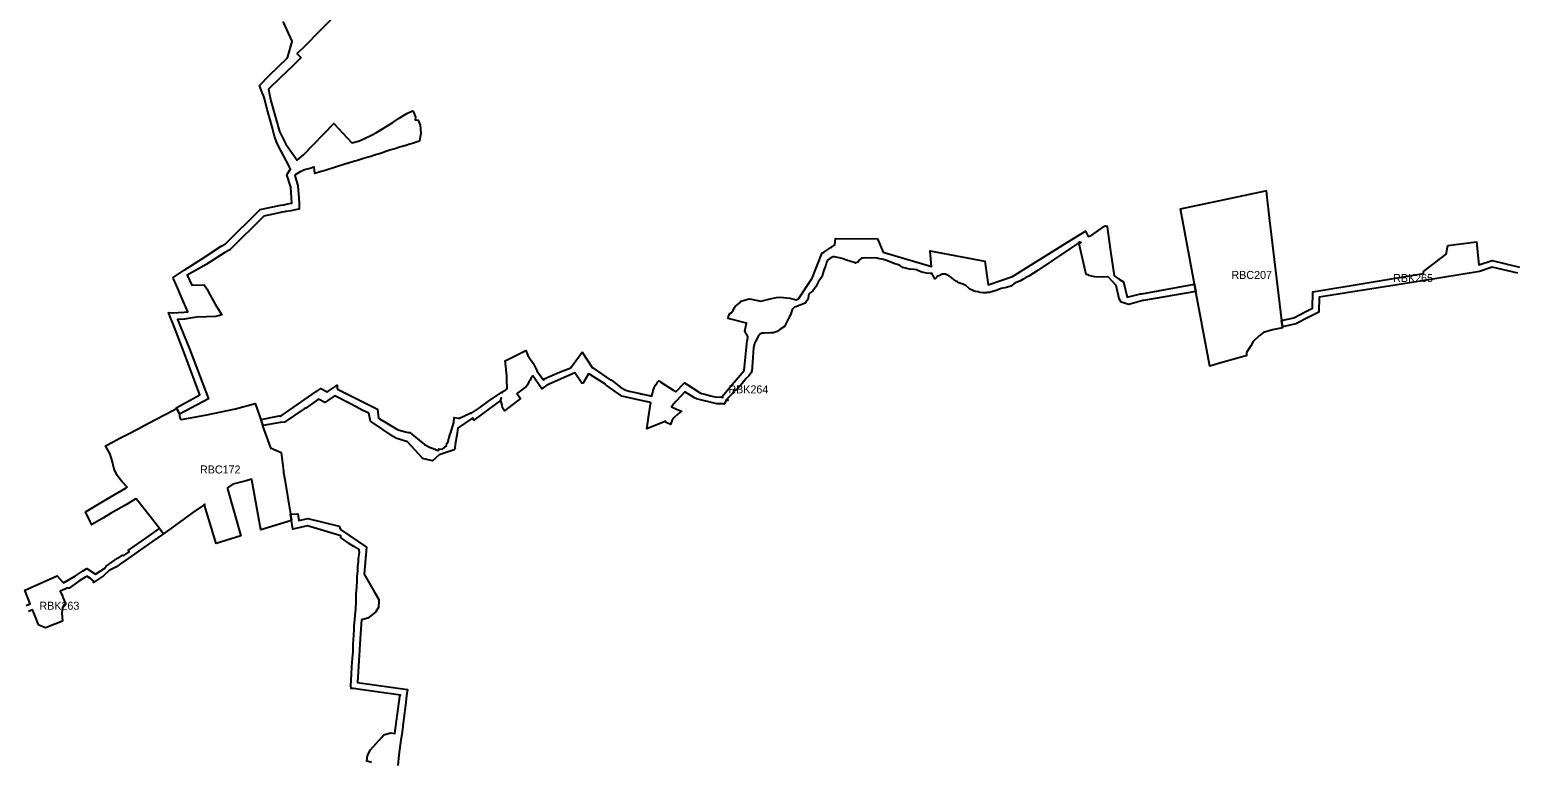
# Model space of a CAD drawing. Extents: x -559776 to -467147, y -1204122 to -1132159.
# Drawn here: x -531983 to -522720, y -1164141 to -1159572 of the extents above; entities that cross this region are included whole.
import ezdxf

# ---------------------------------------------------------------- set-up
doc = ezdxf.new("R2010")
doc.units = 0
doc.layers.add('regionalni_biocentrum_biokoridor', color=7, linetype='Continuous')

msp = doc.modelspace()

# ---------------------------------------------------------------- linework, layer by layer
at = {"layer": 'regionalni_biocentrum_biokoridor'}
for points in [[(-530073.87, -1159482.72), (-530173.93, -1159583.23), (-530265.2, -1159675.35), (-530307.03, -1159716.85), (-530312.02, -1159723.48), (-530289.76, -1159745.15), (-530291.86, -1159749.98), (-530342.2, -1159799.08), (-530415.63, -1159870.42), (-530491.07, -1159944.46), (-530485.06, -1159976.78), (-530475.57, -1160017.31), (-530421.45, -1160208.89), (-530382.52, -1160287.19), (-530311.69, -1160387.08), (-530272.65, -1160352.76), (-530082.99, -1160157.02), (-529971.24, -1160279.21), (-529923.41, -1160265.87), (-529852.16, -1160233.62), (-529817.21, -1160213.2), (-529714.58, -1160151.17), (-529674.14, -1160124.8), (-529626.69, -1160095.91), (-529590.94, -1160078.02), (-529589.97, -1160080.45), (-529587.15, -1160083), (-529584.33, -1160086.06), (-529579.15, -1160100.89), (-529573.27, -1160117.84), (-529574.41, -1160134.9), (-529556.31, -1160137.73), (-529543.15, -1160167.55), (-529540.33, -1160215.23), (-529547.86, -1160268.9), (-529569.54, -1160275.49), (-529584.25, -1160279.86), (-529599.78, -1160285.04), (-529616.1, -1160289.37), (-529631.63, -1160294.52), (-529639.54, -1160296.97), (-529644.42, -1160298.29), (-529649.27, -1160299.59), (-529656.9, -1160302.32), (-529663.98, -1160303.96), (-529678.96, -1160308.32), (-529693.95, -1160313.23), (-529726, -1160323.46), (-529758.04, -1160333.68), (-529765, -1160335.87), (-529779.39, -1160340.25), (-529786.12, -1160342.41), (-529792.47, -1160344.61), (-529807.74, -1160349.4), (-529822.14, -1160354), (-529826.72, -1160355.31), (-529835.24, -1160357.84), (-529839.36, -1160359.16), (-529852.67, -1160363.73), (-529868.61, -1160368.13), (-529883.44, -1160372.48), (-529897.83, -1160377.02), (-529909.84, -1160380.76), (-529923.12, -1160385.09), (-529936, -1160388.41), (-529950.83, -1160392.8), (-529965.23, -1160397.98), (-529980.03, -1160402.17), (-529994.87, -1160407.02), (-530000.76, -1160408.53), (-530008.17, -1160410.68), (-530136.74, -1160451.09), (-530153.01, -1160456.15), (-530161.64, -1160458.76), (-530201.96, -1160470.79), (-530206.75, -1160430.37), (-530207.71, -1160431.01), (-530231.46, -1160439.72), (-530259.91, -1160445.37), (-530293.25, -1160460.2), (-530323.87, -1160478.35), (-530327.08, -1160483.74), (-530307.97, -1160548.09), (-530300.59, -1160654.36), (-530299.85, -1160692.77), (-530304.95, -1160693.97), (-530322.79, -1160697.27), (-530350.66, -1160702.5), (-530382.37, -1160708.54), (-530389.51, -1160709.64), (-530406.95, -1160712.26), (-530414.77, -1160713.77), (-530521.17, -1160736.48), (-530732.84, -1160946.58), (-530763.94, -1160962.99), (-530879.59, -1161038.16), (-530998.66, -1161105.71), (-530969.81, -1161168.24), (-530893.01, -1161165.11), (-530876.02, -1161189.88), (-530856.17, -1161230.71), (-530823.87, -1161285.51), (-530783.56, -1161352.29), (-530820.71, -1161363.03), (-530938.54, -1161366.64), (-530980.63, -1161372.65), (-531015.83, -1161380.36), (-531059.99, -1161382.27), (-530985.44, -1161565.03), (-530866.4, -1161876.46), (-531046.89, -1161973.38), (-531062.73, -1161942.81), (-531065.32, -1161938.2), (-531063.15, -1161931.23), (-530919.3, -1161852.41), (-531020.31, -1161583.07), (-531088.54, -1161405.05), (-531100.87, -1161376.25), (-531116.5, -1161337.78), (-531094.72, -1161340.12), (-531018.58, -1161335.45), (-530995.61, -1161334.04), (-531033.9, -1161242.35), (-531056.76, -1161187.63), (-531066.01, -1161169.84), (-531084.15, -1161127.21), (-531085.88, -1161119.5), (-531080.45, -1161116.09), (-531017.02, -1161074.67), (-530904.22, -1161000.49), (-530786.75, -1160924.15), (-530759.77, -1160909.92), (-530543.49, -1160695.23), (-530423.74, -1160669.67), (-530414.55, -1160667.89), (-530396.27, -1160665.15), (-530390.01, -1160664.19), (-530359.02, -1160658.28), (-530345.6, -1160655.76), (-530352.52, -1160556.15), (-530375.82, -1160477.66), (-530354.51, -1160441.83), (-530355.93, -1160439.82), (-530360.28, -1160429.78), (-530359.42, -1160429.03), (-530378.05, -1160392.19), (-530412.88, -1160330.89), (-530438.68, -1160279.27), (-530454.4, -1160237.16), (-530470.99, -1160172.43), (-530477.45, -1160150.08), (-530500.11, -1160070.77), (-530515.64, -1160001.9), (-530524.65, -1159977.42), (-530525.1, -1159977.87), (-530526.58, -1159975.01), (-530528.68, -1159969.96), (-530530.36, -1159964.29), (-530534.56, -1159953.99), (-530538.55, -1159942.85), (-530540.23, -1159938.23), (-530542.96, -1159930.87), (-530547.51, -1159919.84), (-530488.99, -1159860.66), (-530371.48, -1159747.9), (-530343.23, -1159645.57), (-530343.61, -1159644.79), (-530399.82, -1159520.7)], [(-522686, -1161093), (-522847, -1161055), (-522926, -1161083), (-523269, -1161138), (-523927.07, -1161241.62), (-523929, -1161336), (-523992, -1161368), (-524072, -1161409), (-524156.7, -1161428.16), (-524161.51, -1161388.23), (-524085.75, -1161371.1), (-524010.18, -1161332.37), (-523968.5, -1161311.2), (-523966.41, -1161208.65), (-523276, -1161095), (-523276, -1161087), (-523275.31, -1161082.86), (-523134, -1160974), (-523124, -1160919), (-522945, -1160897), (-522930.24, -1161041.47), (-522845.6, -1161014.23), (-522674.52, -1161054.61)], [(-529848.43, -1164149.26), (-529876.9, -1164140), (-529872.1, -1164105.5), (-529854.3, -1164068.9), (-529784.05, -1163990.31), (-529770.9, -1163975.6), (-529728.1, -1163964), (-529700.91, -1163967.51), (-529669.9, -1163736.2), (-529666.94, -1163727.4), (-529919.25, -1163692.42), (-529960.5, -1163686.7), (-529973.7, -1163685.4), (-529973.8, -1163684.91), (-529976.9, -1163669.2), (-529973.3, -1163599.2), (-529970.3, -1163548.9), (-529966.7, -1163499.5), (-529963, -1163454.4), (-529961.6, -1163408.7), (-529959.8, -1163384), (-529956.6, -1163318.7), (-529954.96, -1163294.49), (-529952.5, -1163258.2), (-529952, -1163253.4), (-529947.1, -1163207.4), (-529946.1, -1163193.1), (-529943.3, -1163141.1), (-529943.4, -1163125.6), (-529943.83, -1163101.75), (-529943.9, -1163097.9), (-529939.5, -1163051.7), (-529937.7, -1163017), (-529937.7, -1163016.5), (-529937.8, -1163008.1), (-529938.1, -1162989), (-529935.5, -1162967.7), (-529934.1, -1162956.3), (-529933.3, -1162945.4), (-529932.5, -1162934.5), (-529932.1, -1162918.3), (-529931.9, -1162915.9), (-529929.5, -1162890), (-529928.4, -1162878.6), (-529926.2, -1162863), (-529922.7, -1162837.4), (-529923.7, -1162823.5), (-529929.5, -1162817), (-529958.7, -1162799.5), (-529959.01, -1162799.3), (-529988.4, -1162780.9), (-529994.3, -1162776.7), (-530029.2, -1162751.6), (-530038.5, -1162744.4), (-530039.3, -1162733.43), (-530247.03, -1162671.46), (-530338.39, -1162691.45), (-530353.73, -1162598.53), (-530308.62, -1162596.24), (-530301.77, -1162637.37), (-530245.48, -1162625.06), (-530049.42, -1162672.5), (-530042.2, -1162693.5), (-529879.4, -1162803.6), (-529893.4, -1162972.8), (-529828.39, -1163084.68), (-529801.3, -1163131.3), (-529801.95, -1163140.59), (-529804.7, -1163180.2), (-529822.8, -1163209.8), (-529870, -1163247.3), (-529910.3, -1163258.5), (-529915.69, -1163342.26), (-529935.5, -1163649.8), (-529921.4, -1163651.76), (-529622.9, -1163693.2), (-529628, -1163732.8), (-529635.36, -1163789.97), (-529645.5, -1163868.8), (-529659.2, -1163972.9), (-529663.8, -1164008), (-529676.8, -1164100.5), (-529684, -1164167.39)], [(-532006.16, -1163169.09), (-531979.28, -1163157.62), (-532013.29, -1163071.8), (-531812.11, -1162982), (-531779.85, -1163018.81), (-531772.86, -1163026.96), (-531697.86, -1162982.32), (-531653.03, -1162954.34), (-531626.71, -1162936.97), (-531571.21, -1162972.5), (-531514.22, -1162935.37), (-531505.73, -1162921.97), (-531435.5, -1162872.33), (-531435, -1162871.98), (-531430.46, -1162871.48), (-531403.7, -1162853.35), (-531394.29, -1162855.75), (-531361.31, -1162833), (-531367.16, -1162824.64), (-531235.86, -1162733.02), (-531172.62, -1162688.05), (-531148.02, -1162719.64), (-531212.86, -1162765.75), (-531368.06, -1162874.05), (-531416.85, -1162908.09), (-531439.96, -1162927.6), (-531485.72, -1162950.05), (-531521.12, -1162982), (-531584.16, -1163024.31), (-531584.98, -1163013.33), (-531603.56, -1163000.06), (-531626.94, -1162985.05), (-531631.41, -1162988.01), (-531675.53, -1163015.54), (-531736.99, -1163058.85), (-531750.04, -1163060.29), (-531792.64, -1163078.32), (-531777.09, -1163113.97), (-531773.39, -1163122.41), (-531759.14, -1163154.96), (-531769.67, -1163164.23), (-531777.26, -1163182.13), (-531782.78, -1163212.82), (-531778.01, -1163265.99), (-531825.7, -1163284.72), (-531884.03, -1163307.75), (-531925.32, -1163290.15), (-531930.27, -1163282.66), (-531945.52, -1163244.92), (-531961.28, -1163204.12), (-531964.83, -1163194.94), (-531990.38, -1163205.84)]]:
    msp.add_lwpolyline(points, dxfattribs=at)
for points in [[(-524555.42, -1161657.29), (-524611, -1161673), (-524698, -1161209), (-524698.29, -1161207.44), (-524706, -1161166), (-524706.72, -1161162.07), (-524793.46, -1160689.89), (-524527.69, -1160634.25), (-524261.92, -1160578.61), (-524259, -1160578), (-524254.15, -1160618.33), (-524238.57, -1160747.8), (-524161.51, -1161388.23), (-524156.7, -1161428.16), (-524156, -1161434), (-524218, -1161446), (-524274, -1161464), (-524301, -1161484), (-524339, -1161520), (-524354, -1161546), (-524381, -1161588), (-524381, -1161608), (-524386, -1161609.41), (-524428.97, -1161621.56)], [(-525251.67, -1160802.38), (-525230.16, -1160954.79), (-525208.24, -1161110.05), (-525173.8, -1161131.34), (-525148.72, -1161146.83), (-525125.77, -1161242.23), (-525043.17, -1161222.36), (-525041.31, -1161222.03), (-525035.2, -1161220.93), (-524706.72, -1161162.07), (-524706, -1161166), (-524698.29, -1161207.44), (-525024.34, -1161263.15), (-525028.95, -1161264.36), (-525116.48, -1161287.3), (-525163.92, -1161273.77), (-525176.94, -1161253.47), (-525194.92, -1161168.86), (-525218.83, -1161143.8), (-525246.2, -1161115.09), (-525249.44, -1161115.32), (-525276.22, -1161117.26), (-525327.81, -1161115.03), (-525366.48, -1161106.46), (-525367.14, -1161103.45), (-525382.06, -1161100.29), (-525427.07, -1160909.49), (-525413.89, -1160900.56), (-525422.34, -1160898.14), (-525430.85, -1160903.92), (-525452.97, -1160918.95), (-525485.24, -1160940.69), (-525682.3, -1161073.47), (-525740.07, -1161111.36), (-525759.19, -1161119.86), (-525773.15, -1161128.32), (-525796.97, -1161141.74), (-525825.77, -1161153.5), (-525853.99, -1161172.8), (-525881.5, -1161182.68), (-525913.07, -1161187.38), (-525938.48, -1161198.11), (-525944.03, -1161199.99), (-525987.61, -1161213.03), (-525999.68, -1161214.09), (-526004.76, -1161215.01), (-526008.1, -1161214.82), (-526012.95, -1161215.25), (-526027.22, -1161214.62), (-526046.87, -1161213.75), (-526057.67, -1161210.1), (-526075.78, -1161206.53), (-526081.87, -1161204.44), (-526094.34, -1161199.12), (-526108.62, -1161191.97), (-526115.77, -1161186.04), (-526134.92, -1161169.15), (-526152.85, -1161160.33), (-526177.47, -1161152.42), (-526187.13, -1161146.72), (-526195.87, -1161141.84), (-526206.48, -1161134.38), (-526222.98, -1161122.18), (-526235.6, -1161111.56), (-526260.55, -1161098.65), (-526281.49, -1161097.93), (-526300.93, -1161110.05), (-526311.29, -1161111.69), (-526317.1, -1161119.15), (-526328, -1161127.43), (-526338.43, -1161107.88), (-526348.99, -1161096.62), (-526344.1, -1161096.66), (-526348.13, -1161096.06), (-526345.36, -1161094.27), (-526348.77, -1161094.33), (-526357.86, -1161093.98), (-526379.65, -1161093.16), (-526415.84, -1161084.57), (-526441.98, -1161071.16), (-526456.54, -1161070.35), (-526485.53, -1161067.15), (-526528.89, -1161056.61), (-526547.67, -1161044.12), (-526560.79, -1161038.73), (-526578.8, -1161035.2), (-526603.29, -1161024.59), (-526629.63, -1161014.46), (-526643.03, -1161009.3), (-526644.73, -1161008.66), (-526644.99, -1161008.56), (-526649.05, -1161007.2), (-526683.06, -1161000.25), (-526688.72, -1160999.31), (-526706.36, -1160996.47), (-526733.26, -1160999.28), (-526759.03, -1160996.74), (-526776.07, -1160998.12), (-526785.95, -1160998.94), (-526801.41, -1161010.94), (-526803.17, -1161012.31), (-526806.71, -1161019.01), (-526808.91, -1161023.17), (-526816.14, -1161026.29), (-526823.25, -1161029.35), (-526826.41, -1161028.31), (-526886.88, -1161008.52), (-526907.89, -1161001.64), (-526955.59, -1160991.22), (-526963.71, -1160991.15), (-526974.41, -1160994.57), (-526984.21, -1161000.65), (-526998.08, -1161010.73), (-527005.85, -1161025.15), (-527009.51, -1161042.78), (-527020.74, -1161074.46), (-527027.01, -1161094.71), (-527032.54, -1161112.56), (-527037.73, -1161121.73), (-527056.06, -1161148.51), (-527070.79, -1161177.85), (-527079.13, -1161188.47), (-527090.38, -1161202.8), (-527101.53, -1161211.05), (-527107.78, -1161215.67), (-527113.79, -1161222.27), (-527116.83, -1161229.32), (-527120.45, -1161250.21), (-527121.53, -1161256.58), (-527134.04, -1161274.65), (-527136.88, -1161278.76), (-527138.26, -1161280.76), (-527168.66, -1161292), (-527185.6, -1161298.27), (-527196.76, -1161302.47), (-527204.21, -1161305.15), (-527214.77, -1161314.54), (-527219.83, -1161322.63), (-527224.72, -1161335), (-527230.15, -1161352), (-527235.19, -1161363.5), (-527244.05, -1161380.73), (-527245.66, -1161383.87), (-527266.91, -1161425.39), (-527267.1, -1161425.53), (-527267.22, -1161425.76), (-527296.03, -1161444.84), (-527312.88, -1161456.75), (-527325.83, -1161462.09), (-527336.13, -1161464.4), (-527353.24, -1161464.95), (-527393.58, -1161466.72), (-527407.2, -1161466.9), (-527420.99, -1161472.8), (-527432.22, -1161488.44), (-527445.05, -1161512.07), (-527453.86, -1161532.75), (-527460.72, -1161559.87), (-527464.63, -1161616.6), (-527469.65, -1161678.94), (-527470.3, -1161685.56), (-527472.05, -1161700.75), (-527476.68, -1161715.98), (-527489.7, -1161732.87), (-527506.32, -1161750.63), (-527532.43, -1161781.55), (-527544.14, -1161796.78), (-527558.28, -1161811.69), (-527574.74, -1161824.62), (-527584.46, -1161830.04), (-527592.15, -1161843.51), (-527622.52, -1161875.41), (-527621.41, -1161888.02), (-527631.28, -1161884.61), (-527634.14, -1161890.65), (-527643.16, -1161909.68), (-527643.83, -1161911.1), (-527644.09, -1161909.39), (-527648.44, -1161908), (-527690.29, -1161909.59), (-527817.82, -1161877.67), (-527830.42, -1161870.21), (-527890.99, -1161834.34), (-527910.98, -1161856.03), (-527921.77, -1161867.73), (-527938, -1161885.33), (-527946.28, -1161894.29), (-527959.22, -1161908.68), (-527972.57, -1161927.75), (-527941.41, -1161941.1), (-527910.26, -1161954.46), (-527931.95, -1161970.22), (-527959.4, -1161995.21), (-527970.6, -1162014.62), (-527980.18, -1162036.98), (-528007.54, -1162025.39), (-528010.68, -1162017.45), (-528019.86, -1162020.41), (-528116.75, -1162060.67), (-528128.53, -1162063.96), (-528120.14, -1162011.58), (-528116.66, -1161990.4), (-528112.63, -1161965.92), (-528109.98, -1161948.12), (-528108.57, -1161938.92), (-528105.98, -1161922.45), (-528102.95, -1161903.03), (-528102.7, -1161901.38), (-528112.26, -1161898.86), (-528121.58, -1161896.78), (-528125.51, -1161895.9), (-528284.23, -1161860.55), (-528380.56, -1161791.04), (-528384.16, -1161788.44), (-528486.45, -1161723.07), (-528490.99, -1161720.42), (-528521.25, -1161772.29), (-528525.41, -1161778.72), (-528533.22, -1161779.29), (-528577.3, -1161715.26), (-528752.01, -1161791.05), (-528783.66, -1161815.69), (-528840.44, -1161734.59), (-528840.53, -1161734.58), (-528841.15, -1161735.41), (-528852.16, -1161750.6), (-528856.63, -1161761.19), (-528865.68, -1161770.88), (-528873.45, -1161790.42), (-528878.9, -1161797.87), (-528903.04, -1161817.45), (-528916.97, -1161827.7), (-528932.86, -1161839.67), (-528938.77, -1161844.39), (-528937.96, -1161845.53), (-528916.44, -1161875.91), (-529017.36, -1161953.34), (-529028.47, -1161933.87), (-529031.64, -1161916.49), (-529040.48, -1161887.59), (-529037.12, -1161870.65), (-529041.06, -1161888.84), (-529111.83, -1161940.83), (-529207.36, -1162011.11), (-529214.42, -1161995.2), (-529220.17, -1161999.22), (-529306.2, -1162059.3), (-529308.67, -1162061.03), (-529309.13, -1162064.21), (-529309.92, -1162072.86), (-529315.19, -1162105.62), (-529316.55, -1162113.5), (-529320.74, -1162140.52), (-529321.94, -1162148.78), (-529325.01, -1162167.72), (-529324.62, -1162167.82), (-529326.2, -1162178.21), (-529325.62, -1162187.31), (-529332.12, -1162196.2), (-529424.1, -1162227.9), (-529466.7, -1162264.06), (-529528.35, -1162250.24), (-529528.14, -1162248.49), (-529622.98, -1162146.85), (-529695.79, -1162122.81), (-529698.32, -1162121.98), (-529712.25, -1162112.61), (-529854.23, -1162017.15), (-529864.22, -1161967.94), (-529905.35, -1161947.56), (-529942.98, -1161928.09), (-529983.34, -1161906.4), (-530077.31, -1161859.36), (-530080.1, -1161861.19), (-530120.79, -1161887.88), (-530139.43, -1161900.11), (-530179.01, -1161880.45), (-530258.88, -1161935.36), (-530264.4, -1161937.99), (-530267.42, -1161940.01), (-530391.69, -1162023.36), (-530418.58, -1162024.42), (-530525.15, -1162044.24), (-530537.37, -1162005.91), (-530425.32, -1161983.31), (-530416.03, -1161985.92), (-530413, -1161983.85), (-530192.92, -1161832.58), (-530188.22, -1161829.35), (-530165.09, -1161813.45), (-530124.14, -1161834.09), (-530120.93, -1161831.65), (-530071.49, -1161797.75), (-530062.65, -1161792.05), (-530060.99, -1161794.68), (-530062.74, -1161799.52), (-530062.77, -1161802.09), (-530062.87, -1161811.57), (-530059.7, -1161816.23), (-529810.51, -1161942.84), (-529803.31, -1161998.09), (-529797.61, -1162001.63), (-529758.62, -1162025.06), (-529716.23, -1162050.82), (-529689.88, -1162066.56), (-529682.1, -1162071.24), (-529634.37, -1162083.99), (-529616.98, -1162088.14), (-529616.22, -1162088.09), (-529606.2, -1162087.45), (-529606.57, -1162089.21), (-529517.5, -1162163.53), (-529507.22, -1162167.32), (-529480.16, -1162180.4), (-529479.56, -1162180.65), (-529451.28, -1162192.32), (-529444.95, -1162194.93), (-529430.96, -1162200.7), (-529427.55, -1162193), (-529426.47, -1162190.57), (-529403.98, -1162191.15), (-529378.71, -1162170.37), (-529376.58, -1162154.09), (-529373.1, -1162154.87), (-529371.46, -1162150.28), (-529355.45, -1162095.56), (-529354.72, -1162093.18), (-529333.66, -1162024.56), (-529331.38, -1161993.87), (-529303.13, -1161997.89), (-529298.73, -1161997.18), (-529232.25, -1161967.85), (-529226.6, -1161965.49), (-529222.72, -1161967.9), (-529171.98, -1161932.71), (-529115.75, -1161892.19), (-529040.68, -1161840.41), (-529035.34, -1161836.66), (-529030.98, -1161837.51), (-529031.43, -1161839.92), (-529030.43, -1161840.29), (-529029.77, -1161837.27), (-529031.9, -1161836.47), (-529024.44, -1161831.14), (-529017.96, -1161827.03), (-529011.48, -1161822.91), (-529005.61, -1161818.71), (-528999.75, -1161814.51), (-529000.55, -1161795.97), (-529001.35, -1161777.43), (-529001.58, -1161766.26), (-529001.81, -1161755.09), (-529002.01, -1161744.47), (-529002.2, -1161733.85), (-529004.2, -1161714.64), (-529006.19, -1161695.43), (-529008.64, -1161671.44), (-529009.71, -1161663.12), (-529010.63, -1161654.76), (-529012.7, -1161640.71), (-528949.99, -1161609.39), (-528887.27, -1161578.07), (-528883.05, -1161575.63), (-528870.56, -1161606.93), (-528854.22, -1161630.96), (-528837.88, -1161654.99), (-528820.68, -1161688.14), (-528812.25, -1161697.61), (-528814.13, -1161702.47), (-528776.89, -1161755.45), (-528774.97, -1161758.2), (-528769.89, -1161756.04), (-528768.94, -1161752.14), (-528672.29, -1161711.73), (-528603.3, -1161683.01), (-528601.28, -1161680.44), (-528531.61, -1161586.45), (-528468.42, -1161681.73), (-528464.66, -1161684.31), (-528356.5, -1161758.5), (-528350.58, -1161759.04), (-528318.78, -1161784.12), (-528290.43, -1161806.26), (-528259.37, -1161824.18), (-528237.68, -1161829.15), (-528199.06, -1161837.88), (-528179.18, -1161842.45), (-528169.51, -1161844.53), (-528164.99, -1161845.27), (-528160.01, -1161846.37), (-528153.73, -1161848.1), (-528141.76, -1161850.84), (-528115.39, -1161856.67), (-528111.45, -1161857.55), (-528105.87, -1161858.78), (-528096.3, -1161860.94), (-528095.61, -1161856.74), (-528092.75, -1161844.99), (-528090.78, -1161837.5), (-528087.34, -1161826.22), (-528084.92, -1161818.29), (-528081.87, -1161809.71), (-528077.57, -1161801.08), (-528075.19, -1161796.29), (-528072.94, -1161791.78), (-528063.18, -1161777.03), (-528060.08, -1161772.63), (-528053.05, -1161764.55), (-528048.48, -1161767.49), (-528040, -1161772.95), (-527958.75, -1161825.27), (-527945.78, -1161833.62), (-527895.8, -1161781.3), (-527892.13, -1161777.47), (-527858.74, -1161799.34), (-527855.98, -1161801.11), (-527839.87, -1161811.49), (-527798.6, -1161837.76), (-527786.03, -1161843.46), (-527766.02, -1161849.22), (-527730.1, -1161857.87), (-527691.38, -1161867.21), (-527665.31, -1161864.75), (-527652.19, -1161869.95), (-527656.74, -1161862.92), (-527615.37, -1161813.73), (-527606.14, -1161802.75), (-527518.9, -1161700.52), (-527500.31, -1161513.22), (-527499.14, -1161511.54), (-527496.74, -1161487.99), (-527516.08, -1161454.45), (-527504.52, -1161404.33), (-527620.16, -1161375.96), (-527616.46, -1161364.06), (-527611.51, -1161347.11), (-527600.93, -1161341.21), (-527587.8, -1161326.39), (-527579.61, -1161307.82), (-527576.04, -1161301.33), (-527543, -1161274.71), (-527539.49, -1161267.16), (-527487.69, -1161253.38), (-527473.47, -1161255.02), (-527416.3, -1161267.31), (-527356.81, -1161253.42), (-527317.98, -1161245.12), (-527293.66, -1161242.43), (-527234.45, -1161248.79), (-527208.72, -1161254.25), (-527194.97, -1161258.27), (-527179.55, -1161251.92), (-527095.29, -1161123.14), (-527031.62, -1160965.19), (-527020.98, -1160962.7), (-527021.3, -1160962.22), (-526977.43, -1160931.76), (-526974.14, -1160929.48), (-526953, -1160914.79), (-526949.15, -1160875.19), (-526686.78, -1160877.89), (-526651.95, -1160961.11), (-526348.73, -1161051.72), (-526350.29, -1161031.96), (-526350.48, -1161029.95), (-526358.38, -1160953.51), (-526356.47, -1160953.85), (-526159.41, -1160991.23), (-526016.83, -1161018.27), (-525994.64, -1161166.14), (-525843.11, -1161112.47), (-525499.31, -1160899.8), (-525386.32, -1160829.91), (-525370.75, -1160863.06), (-525354.06, -1160859.24), (-525268.92, -1160799.49), (-525262.5, -1160797.65), (-525252.07, -1160799.52)], [(-530353.73, -1162598.53), (-530347.56, -1162636.36), (-530538.75, -1162694.95), (-530595.71, -1162384.27), (-530596.46, -1162380.07), (-530630.66, -1162388.78), (-530714.93, -1162410.23), (-530748.23, -1162433.89), (-530746.97, -1162438.65), (-530664.99, -1162733.73), (-530819.16, -1162781.65), (-530891.32, -1162541.38), (-530889.67, -1162535.1), (-530906.18, -1162547.04), (-530963.02, -1162588.04), (-531071.28, -1162665.35), (-531148.02, -1162719.64), (-531172.62, -1162688.05), (-531231.31, -1162612.68), (-531318.45, -1162501.3), (-531323.47, -1162505.04), (-531378.14, -1162536.74), (-531477.32, -1162594.49), (-531521.83, -1162620.54), (-531590.26, -1162660.86), (-531595.16, -1162663.77), (-531604.83, -1162644.11), (-531634.87, -1162583.77), (-531630.81, -1162581.54), (-531505.14, -1162507.11), (-531379.48, -1162432.68), (-531374.6, -1162429.82), (-531405.7, -1162395.33), (-531437.1, -1162356.39), (-531443.75, -1162341.35), (-531454.1, -1162325.42), (-531469.6, -1162256.67), (-531481.85, -1162219.41), (-531509.39, -1162170.91), (-531504.72, -1162168.04), (-531462.61, -1162145.97), (-531420.49, -1162123.9), (-531365.8, -1162095.38), (-531305.67, -1162064.28), (-531268.73, -1162044.51), (-531196.56, -1162007.02), (-531133.35, -1161973.93), (-531093.25, -1161953.19), (-531065.32, -1161938.2), (-531062.73, -1161942.81), (-531046.89, -1161973.38), (-531047.75, -1161982.6), (-531045.45, -1161993.27), (-531036.86, -1162005.86), (-530887.78, -1161978.79), (-530697.54, -1161939.54), (-530573.49, -1161905.56), (-530550.5, -1161977.9), (-530529.48, -1162042.06), (-530528.51, -1162046.86), (-530479.36, -1162182.64), (-530411.2, -1162212.44), (-530397.42, -1162329.96), (-530396.48, -1162336.52), (-530389.23, -1162380.96)]]:
    msp.add_lwpolyline(points, close=True, dxfattribs=at)

# ---------------------------------------------------------------- texts
for s, p in [('RBC207', (-524474.73, -1161128.83)), ('RBK265', (-523464.9, -1161147.95)), ('RBK264', (-527617.83, -1161843.57)), ('RBC172', (-530919.04, -1162343.6)), ('RBK263', (-531922.24, -1163194.52))]:
    msp.add_text(s, height=50, dxfattribs=at).set_placement(p)

doc.saveas('drawing.dxf')
